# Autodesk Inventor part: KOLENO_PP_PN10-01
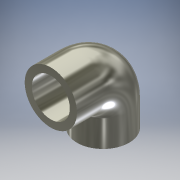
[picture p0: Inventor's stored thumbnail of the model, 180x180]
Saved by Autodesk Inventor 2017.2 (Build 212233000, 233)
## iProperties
Created: 2016-11
Part Number: KOLENO_PP_PN10-01
Material: Polypropylen
Document SubType Name: Modeling
Designer: CADstudio
Mass: 14.3031 g
Surface Area: 79.3778 cm^2
Volume: 15.91 cm^3
Density: 0.899 g/cm^3
Appearance: Hladká – popel
Vendor: KOWA
Categories: <MemberInstance><Categories><Category DisplayName="" InternalName="4347fa0f-2144-441d-94cd-e3e15c92b736" Mnemonic="TUBEANDPIPE"><CategoryParameter DisplayName="
Mass: 0,014
Author: CADstudio
Title: KOLENO PP PN10
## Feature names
1. Tažení1
2. Vysunutí1 [Extrusion]
3. Vysunutí2 [Extrusion]
## Parameters: EXTERNI = 27.5 mm, VNI = 16.2 mm, H_OSA = 27.5 mm, d3 = 27.5 mm, d4 = 13.75 mm, d5 = 0, d6 = 0, Z_OSA = 13 mm, d8 = 14.5 mm, d9 = 0, d11 = 14.5 mm, d12 = 0
